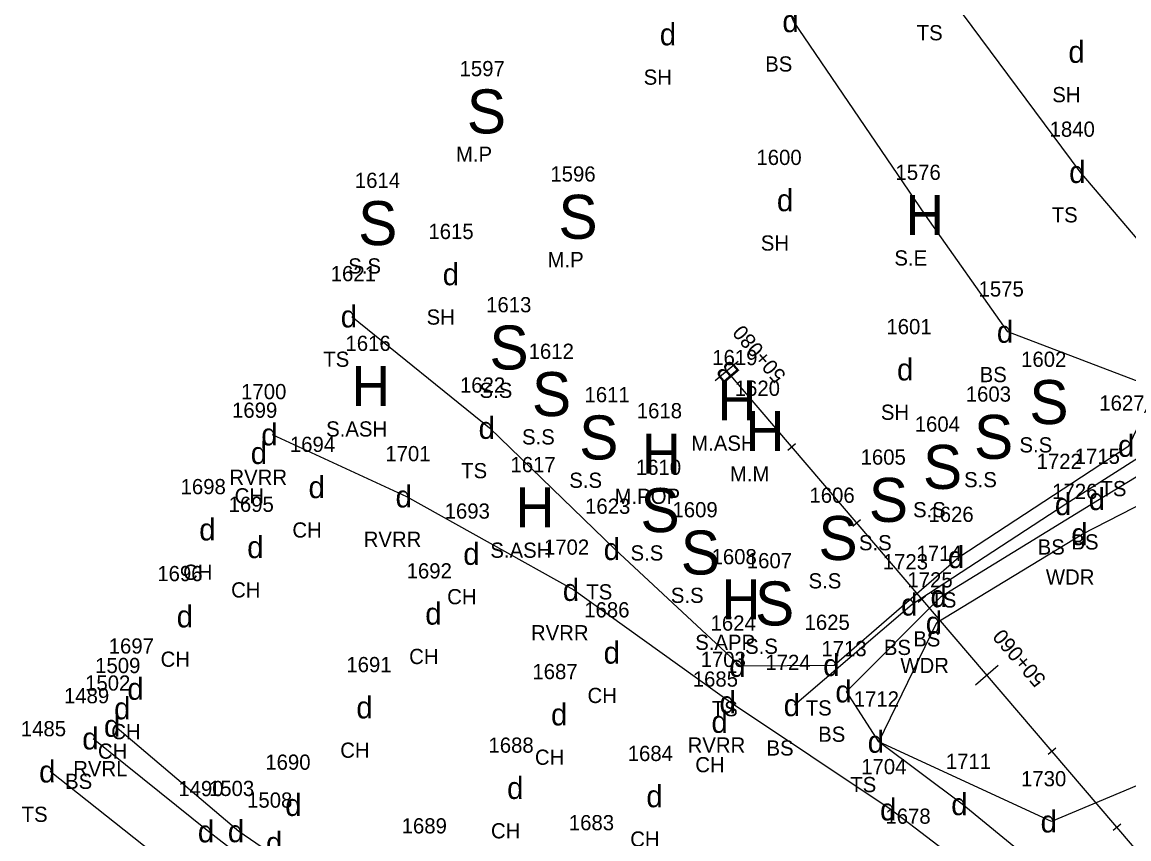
# Model space of a CAD drawing. Extents: x 461160 to 461373, y 202903 to 203086.
# Drawn here: x 461258.8 to 461314.2, y 202986.1 to 203027 of the extents above; entities that cross this region are included whole.
import ezdxf

# ---------------------------------------------------------------- set-up
doc = ezdxf.new("R2010")
doc.units = 0
for name, color, linetype in [('Level 12', 7, 'Continuous'), ('Level 13', 7, 'Continuous'), ('Level 14', 7, 'Continuous'), ('Level 17', 7, 'Continuous'), ('Level 46', 7, 'Continuous'), ('Level 47', 7, 'Continuous'), ('Level 48', 7, 'Continuous'), ('Level 49', 7, 'Continuous')]:
    doc.layers.add(name, color=color, linetype=linetype)

msp = doc.modelspace()

# ---------------------------------------------------------------- linework, layer by layer
at = {"layer": 'Level 12'}
msp.add_line((461346.056, 202948.738), (461294.056, 203009.532), dxfattribs=at)
at = {"layer": 'Level 13'}
for points in [[(461293.486, 203009.044), (461294.626, 203010.02)], [(461293.866, 203009.369), (461294.246, 203009.695)], [(461297.116, 203005.57), (461297.496, 203005.895)], [(461300.366, 203001.771), (461300.746, 203002.096)], [(461303.616, 202997.971), (461303.996, 202998.296)], [(461306.486, 202993.846), (461307.626, 202994.821)], [(461310.116, 202990.372), (461310.496, 202990.697)], [(461313.366, 202986.572), (461313.746, 202986.897)]]:
    msp.add_lwpolyline(points, dxfattribs=at)
at = {"layer": 'Level 14'}
msp.add_lwpolyline([(461301.65, 202990.994), (461304.551, 202996.947), (461311.823, 203001.37), (461316.945, 203004), (461316.225, 202999.291), (461317.949, 202990.224), (461310.29, 202987.008), (461301.65, 202990.994)], dxfattribs=at)
at = {"layer": 'Level 17'}
for points in [[(461271.342, 203006.356), (461278.053, 203003.256), (461286.412, 202998.583), (461294.243, 202992.971), (461302.269, 202987.612), (461311.447, 202980.59), (461317.239, 202975.481), (461319.309, 202973.643)], [(461263.48, 202991.79), (461269.671, 202986.522), (461276.694, 202981.707), (461283.863, 202976.623)]]:
    msp.add_lwpolyline(points, dxfattribs=at)
at = {"layer": 'Level 48'}
for points in [[(461315.541, 203008.651), (461308.105, 203011.488), (461303.992, 203017.318), (461297.386, 203027.014), (461293.414, 203037.031), (461290.876, 203049.461), (461296.168, 203054.025)], [(461315.541, 203008.651), (461308.105, 203011.488), (461303.992, 203017.318), (461297.386, 203027.014), (461293.414, 203037.031), (461290.876, 203049.461), (461296.168, 203054.025)], [(461321.327, 202988.274), (461324.106, 202992.683), (461325.466, 203002.03), (461321.733, 203002.708), (461316.945, 203004), (461321.225, 203006.69), (461324.085, 203007.39), (461327.398, 203011.243), (461327.047, 203014.732), (461324.41, 203015.108), (461324.41, 203015.108), (461321.477, 203013.865), (461317.057, 203013.221), (461311.718, 203019.474), (461304.97, 203028.576), (461302.488, 203033.292)], [(461321.327, 202988.274), (461324.106, 202992.683), (461325.466, 203002.03), (461321.733, 203002.708), (461316.945, 203004), (461321.225, 203006.69), (461324.085, 203007.39), (461327.398, 203011.243), (461327.047, 203014.732), (461324.41, 203015.108), (461324.41, 203015.108), (461321.477, 203013.865), (461317.057, 203013.221), (461311.718, 203019.474), (461304.97, 203028.576), (461302.488, 203033.292)], [(461321.29, 202974.86), (461317.717, 202978.484), (461312.473, 202982.423), (461305.824, 202987.874), (461301.65, 202990.994), (461300.034, 202993.51), (461304.787, 202998.277), (461312.691, 203003.124), (461318.698, 203006.786), (461322.707, 203009.684), (461325.345, 203012.481), (461324.782, 203012.846), (461322.016, 203009.952), (461316.942, 203006.65), (461311.004, 203002.871), (461303.318, 202997.851), (461297.451, 202992.823)], [(461321.29, 202974.86), (461317.717, 202978.484), (461312.473, 202982.423), (461305.824, 202987.874), (461301.65, 202990.994), (461300.034, 202993.51), (461304.787, 202998.277), (461312.691, 203003.124), (461318.698, 203006.786), (461322.707, 203009.684), (461325.345, 203012.481), (461324.782, 203012.846), (461322.016, 203009.952), (461316.942, 203006.65), (461311.004, 203002.871), (461303.318, 202997.851), (461297.451, 202992.823)], [(461275.313, 203012.255), (461282.203, 203006.684), (461288.456, 203000.628), (461294.729, 202994.786), (461299.425, 202994.826), (461305.655, 203000.223), (461314.155, 203005.787), (461315.541, 203008.651)], [(461275.313, 203012.255), (461282.203, 203006.684), (461288.456, 203000.628), (461294.729, 202994.786), (461299.425, 202994.826), (461305.655, 203000.223), (461314.155, 203005.787), (461315.541, 203008.651)], [(461262.397, 202991.157), (461268.172, 202986.514), (461275.177, 202981.097), (461279.904, 202974.246), (461281.802, 202966.659), (461283.93, 202965.263), (461286.001, 202961.968), (461287.188, 202964.973), (461289.154, 202965.814)], [(461262.397, 202991.157), (461268.172, 202986.514), (461275.177, 202981.097), (461279.904, 202974.246), (461281.802, 202966.659), (461283.93, 202965.263), (461286.001, 202961.968), (461287.188, 202964.973), (461289.154, 202965.814)], [(461283.063, 202965.154), (461280.895, 202965.708), (461278.537, 202972.974), (461274.336, 202978.356), (461268.122, 202983.257), (461260.239, 202989.507)], [(461283.063, 202965.154), (461280.895, 202965.708), (461278.537, 202972.974), (461274.336, 202978.356), (461268.122, 202983.257), (461260.239, 202989.507)]]:
    msp.add_lwpolyline(points, dxfattribs=at)

# ---------------------------------------------------------------- texts
at = {"layer": 'Level 12'}
msp.add_text('B', height=1, rotation=130.5419, dxfattribs=at).set_placement((461294.761, 203009.477))
at = {"layer": 'Level 13'}
for s, p in [('50+080', (461297.056, 203009.332)), ('50+060', (461310.056, 202994.134))]:
    msp.add_text(s, height=0.75, rotation=130.5419, dxfattribs=at).set_placement(p)
at = {"layer": 'Level 14'}
for s, height, p in [('S', 2.2, (461281.066, 203021.403)), ('S', 2.2, (461275.634, 203015.818)), ('S', 2.2, (461285.644, 203016.135)), ('H', 2, (461302.992, 203016.318)), ('S', 2.2, (461282.195, 203009.601)), ('H', 2, (461275.305, 203007.77)), ('S', 2.2, (461284.319, 203007.273)), ('H', 2, (461293.599, 203007.06)), ('S', 2.2, (461309.179, 203006.874)), ('H', 2, (461294.999, 203005.524)), ('S', 2.2, (461286.681, 203005.105)), ('S', 2.2, (461306.412, 203005.134)), ('H', 2, (461289.825, 203004.402)), ('S', 2.2, (461303.862, 203003.633)), ('S', 2.2, (461301.156, 203001.984)), ('H', 2, (461283.513, 203001.709)), ('S', 2.2, (461289.743, 203001.472)), ('S', 2.2, (461298.639, 203000.078)), ('S', 2.2, (461291.757, 202999.353)), ('H', 2, (461293.808, 202997.105)), ('S', 2.2, (461295.469, 202996.807))]:
    msp.add_text(s, height=height, dxfattribs=at).set_placement(p)
at = {"layer": 'Level 46'}
for s, p in [(' TS  ', (461303.268, 203026.056)), (' BS  ', (461295.696, 203024.494)), (' SH  ', (461289.622, 203023.836)), (' SH  ', (461310.043, 203022.962)), (' M.P  ', (461280.24, 203019.983)), (' TS  ', (461310.016, 203016.954)), (' SH  ', (461295.477, 203015.544)), (' S.S  ', (461274.858, 203014.398)), (' M.P  ', (461284.818, 203014.715)), (' S.E  ', (461302.152, 203014.798)), (' SH  ', (461278.774, 203011.843)), (' TS  ', (461273.611, 203009.735)), (' BS  ', (461306.415, 203008.968)), (' S.S  ', (461281.419, 203008.181)), (' SH  ', (461301.479, 203007.085)), (' S.ASH  ', (461273.753, 203006.25)), (' S.S  ', (461283.543, 203005.853)), (' M.ASH  ', (461291.999, 203005.54)), (' S.S  ', (461308.403, 203005.454)), (' TS  ', (461280.501, 203004.164)), (' M.M  ', (461293.932, 203004.004)), (' RVRR  ', (461268.919, 203003.836)), (' S.S  ', (461285.905, 203003.685)), (' S.S  ', (461305.636, 203003.714)), (' CH  ', (461269.179, 203002.907)), (' M.POP  ', (461288.168, 203002.882)), (' TS  ', (461312.453, 203003.267)), (' S.S  ', (461303.086, 203002.213)), (' CH  ', (461272.067, 203001.2)), (' RVRR  ', (461275.63, 203000.736)), (' S.S  ', (461300.38, 203000.564)), (' BS  ', (461311.001, 203000.604)), (' S.ASH  ', (461281.961, 203000.189)), (' S.S  ', (461288.967, 203000.052)), (' BS  ', (461309.314, 203000.351)), (' CH  ', (461266.605, 202999.088)), (' S.S  ', (461297.863, 202998.658)), (' WDR  ', (461309.723, 202998.85)), (' CH  ', (461269.004, 202998.204)), (' CH  ', (461279.802, 202997.866)), (' TS  ', (461286.754, 202998.108)), (' S.S  ', (461290.981, 202997.933)), (' TS  ', (461303.953, 202997.703)), (' RVRR  ', (461283.989, 202996.063)), (' S.APP  ', (461292.199, 202995.585)), (' BS  ', (461303.097, 202995.757)), (' S.S  ', (461294.693, 202995.387)), (' BS  ', (461301.628, 202995.331)), (' CH  ', (461265.48, 202994.741)), (' CH  ', (461277.902, 202994.878)), (' WDR  ', (461302.451, 202994.427)), (' CH  ', (461286.817, 202992.929)), (' TS  ', (461293.027, 202992.266)), (' TS  ', (461297.723, 202992.306)), (' CH  ', (461263.013, 202991.121)), (' BS  ', (461298.344, 202990.99)), (' CH  ', (461262.35, 202990.145)), (' CH  ', (461274.458, 202990.192)), (' RVRR  ', (461291.82, 202990.451)), (' BS  ', (461295.761, 202990.303)), (' CH  ', (461284.188, 202989.841)), (' CH  ', (461292.203, 202989.468)), (' RVRL  ', (461261.114, 202989.27)), (' BS  ', (461260.707, 202988.637)), (' TS  ', (461299.948, 202988.474)), (' TS  ', (461258.537, 202986.987)), (' CH  ', (461281.992, 202986.164)), (' CH  ', (461288.952, 202985.75))]:
    msp.add_text(s, height=0.76, dxfattribs=at).set_placement(p)
at = {"layer": 'Level 47'}
for p in [(461296.836, 203026.464), (461290.708, 203025.806), (461311.129, 203024.932), (461311.168, 203018.924), (461296.563, 203017.514), (461279.86, 203013.813), (461274.763, 203011.705), (461307.555, 203010.938), (461302.565, 203009.055), (461270.792, 203005.806), (461281.653, 203006.134), (461313.605, 203005.237), (461270.265, 203004.877), (461273.153, 203003.17), (461277.503, 203002.706), (461312.141, 203002.574), (461310.454, 203002.321), (461267.691, 203001.058), (461311.273, 203000.82), (461270.09, 203000.174), (461280.888, 202999.836), (461287.906, 203000.078), (461305.105, 202999.673), (461285.862, 202998.033), (461304.237, 202997.727), (461278.988, 202996.848), (461302.768, 202997.301), (461266.566, 202996.711), (461304.001, 202996.397), (461287.903, 202994.899), (461294.179, 202994.236), (461298.875, 202994.276), (461264.099, 202993.091), (461299.484, 202992.96), (461293.693, 202992.421), (461263.436, 202992.115), (461275.544, 202992.162), (461296.901, 202992.273), (461285.274, 202991.811), (461293.289, 202991.438), (461262.93, 202991.24), (461261.847, 202990.607), (461301.1, 202990.444), (461259.689, 202988.957), (461283.078, 202988.134), (461290.038, 202987.72), (461271.988, 202987.285), (461301.719, 202987.062), (461305.274, 202987.324), (461309.74, 202986.458), (461267.622, 202985.964), (461269.121, 202985.972), (461271.027, 202985.388)]:
    msp.add_text('d', height=1.1, dxfattribs=at).set_placement(p)
at = {"layer": 'Level 49'}
for s, p in [(' 1597 ', (461280.422, 203024.263)), (' 1840 ', (461309.911, 203021.234)), (' 1600 ', (461295.258, 203019.824)), (' 1596 ', (461284.961, 203018.995)), (' 1576 ', (461302.209, 203019.078)), (' 1614 ', (461275.188, 203018.678)), (' 1615 ', (461278.864, 203016.123)), (' 1621 ', (461273.982, 203014.015)), (' 1575 ', (461306.361, 203013.248)), (' 1613 ', (461281.749, 203012.461)), (' 1601 ', (461301.754, 203011.365)), (' 1616 ', (461274.72, 203010.53)), (' 1612 ', (461283.873, 203010.133)), (' 1619 ', (461293.05, 203009.82)), (' 1602 ', (461308.487, 203009.734)), (' 1622 ', (461280.441, 203008.444)), (' 1620 ', (461294.174, 203008.284)), (' 1700 ', (461269.505, 203008.116)), (' 1611 ', (461286.665, 203007.965)), (' 1603 ', (461305.72, 203007.994)), (' 1699 ', (461269.05, 203007.187)), (' 1618 ', (461289.279, 203007.162)), (' 1627 ', (461312.393, 203007.547)), (' 1604 ', (461303.17, 203006.493)), (' 1694 ', (461271.941, 203005.48)), (' 1701 ', (461276.71, 203005.016)), (' 1617 ', (461282.967, 203004.469)), (' 1605 ', (461300.464, 203004.844)), (' 1722 ', (461309.26, 203004.631)), (' 1715 ', (461311.163, 203004.884)), (' 1610 ', (461289.234, 203004.332)), (' 1698 ', (461266.479, 203003.368)), (' 1606 ', (461297.908, 203002.938)), (' 1726 ', (461310.04, 203003.13)), (' 1695 ', (461268.878, 203002.484)), (' 1623 ', (461286.694, 203002.388)), (' 1609 ', (461291.062, 203002.213)), (' 1693 ', (461279.676, 203002.146)), (' 1626 ', (461303.854, 203001.983)), (' 1702 ', (461284.638, 203000.343)), (' 1714 ', (461303.259, 203000.037)), (' 1608 ', (461293.016, 202999.865)), (' 1607 ', (461294.777, 202999.667)), (' 1723 ', (461301.574, 202999.611)), (' 1696 ', (461265.315, 202999.021)), (' 1692 ', (461277.776, 202999.158)), (' 1725 ', (461302.807, 202998.707)), (' 1686 ', (461286.652, 202997.209)), (' 1624 ', (461292.967, 202996.546)), (' 1625 ', (461297.663, 202996.586)), (' 1697 ', (461262.887, 202995.401)), (' 1713 ', (461298.506, 202995.27)), (' 1691 ', (461274.763, 202994.472)), (' 1703 ', (461292.469, 202994.731)), (' 1724 ', (461295.707, 202994.583)), (' 1509 ', (461262.209, 202994.425)), (' 1687 ', (461284.062, 202994.121)), (' 1502 ', (461261.706, 202993.55)), (' 1685 ', (461292.077, 202993.748)), (' 1489 ', (461260.65, 202992.917)), (' 1712 ', (461300.122, 202992.754)), (' 1485 ', (461258.495, 202991.267)), (' 1688 ', (461281.866, 202990.444)), (' 1684 ', (461288.826, 202990.03)), (' 1690 ', (461270.713, 202989.595)), (' 1711 ', (461304.726, 202989.634)), (' 1704 ', (461300.495, 202989.372)), (' 1730 ', (461308.483, 202988.768)), (' 1490 ', (461266.365, 202988.274)), (' 1503 ', (461267.897, 202988.282)), (' 1508 ', (461269.803, 202987.698)), (' 1678 ', (461301.704, 202986.894)), (' 1689 ', (461277.527, 202986.411)), (' 1683 ', (461285.883, 202986.569))]:
    msp.add_text(s, height=0.76, dxfattribs=at).set_placement(p)

doc.saveas('drawing.dxf')
